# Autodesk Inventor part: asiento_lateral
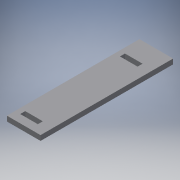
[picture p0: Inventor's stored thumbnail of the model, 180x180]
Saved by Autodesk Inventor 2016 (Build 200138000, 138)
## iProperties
Created: 2017-06
Part Number: asiento_lateral
Material: Generic
Document SubType Name: Modeling
Designer: laboratorioesan
Density: 1 g/cm^3
Appearance: Default
Author: laboratorioesan
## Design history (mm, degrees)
sketch "Sketch1"
  geometry: L1 (27.824, 0)-(92.824, 0) reference; L2 (92.824, 0)-(92.824, 18.5) reference; L3 (27.824, 18.5)-(92.824, 18.5) reference; L4 (27.824, 0)-(27.824, 18.5) reference; L5 (132.824, 0)-(132.824, 18.5) reference; L6 (92.824, -350)-(27.824, -350) reference; L7 (27.824, -350)-(27.824, -368.5) reference; L8 (92.824, -368.5)-(27.824, -368.5) reference; L9 (92.824, -350)-(92.824, -368.5) reference; L10 (132.824, -350)-(132.824, -368.5) reference; L11 (-526.937, -398.5)-(8.357, -398.5) reference; L12 (132.824, 91.5)-(8.324, 91.5); L13 (8.324, 91.5)-(8.324, -398.5); L14 (8.324, -398.5)-(132.824, -398.5); L15 (132.824, -398.5)-(132.824, 91.5); L16 (8.357, 91.5)-(-526.937, 91.5) reference; 1 further point
  constraints: 8 end point, 2 horizontal alignment, 2 parallel, 1 horizontal, 1 perpendicular, 1 vertical alignment
  dimensions: "d0" = 124.5 distance of L13.end L14.end
extrude "Extrusion1" new body sketch "Sketch1" distance "d1" = 18.5; taper "d2" = 0 deg
body "Solid1"
node "Reference1"
node "Reference2"
node "Reference3"
node "Reference4"
node "Reference5"
node "Reference6"
